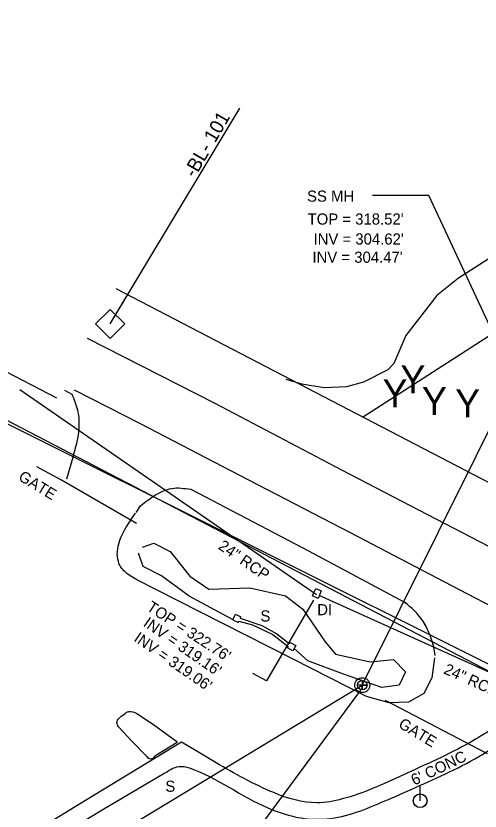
# Model space of a CAD drawing. Extents: x 2057786 to 2059508, y 687766 to 689280.
# Drawn here: x 2058201.2 to 2058367.9, y 688984.5 to 689270 of the extents above; entities that cross this region are included whole.
import ezdxf

# ---------------------------------------------------------------- set-up
doc = ezdxf.new("R2010")
doc.units = 0
for name, color, linetype in [('CTL Supplemental Horizontal and Vertical CELL', 7, 'Continuous'), ('CTL Supplemental Horizontal and Vertical Text', 7, 'Continuous'), ('Exist Horizontal Baseline Alignment Station Label', 7, 'Continuous'), ('Exist Horizontal Baseline Alignment Tick small', 7, 'Continuous'), ('Exist Other Culture Area Outline', 7, 'Continuous'), ('Exist Other Culture Gate', 7, 'Continuous'), ('Exist Other Culture Gate Text', 7, 'Continuous'), ('Exist Other Culture Sign CELL', 7, 'Continuous'), ('Exist Other Culture Sign Text', 7, 'Continuous'), ('Exist Property Line', 7, 'Continuous'), ('Exist Right of Way Line', 7, 'Continuous'), ('Exist Roads Curbs', 7, 'Continuous'), ('Exist Roads EOP', 7, 'Continuous'), ('Exist Roads EOP Other', 7, 'Continuous'), ('Exist Roads EOP Text', 7, 'Continuous'), ('Exist Roads EOT', 7, 'Continuous'), ('Exist Structure Minor Drop Inlet', 7, 'Continuous'), ('Exist Structure Minor Drop Inlet Leader', 7, 'Continuous'), ('Exist Structure Minor Drop Inlet Text', 7, 'Continuous'), ('Exist Structure Minor Pipes RCP 24 Inch', 7, 'Continuous'), ('Exist Structure Minor Pipes RCP 24 Inch Invert', 7, 'Continuous'), ('Exist Structure Minor Pipes RCP 24 Inch Text', 7, 'Continuous'), ('Exist Utilities Gas UG Line', 7, 'Continuous'), ('Exist Utilities Other Pole CELL', 7, 'Continuous'), ('Exist Utilities Power Pole CELL', 7, 'Continuous'), ('Exist Utilities Sanitary Sewer Forced Main', 7, 'Continuous'), ('Exist Utilities Sanitary Sewer Manhole CELL', 7, 'Continuous'), ('Exist Utilities Sanitary Sewer Manhole Leader', 7, 'Continuous'), ('Exist Utilities Sanitary Sewer Manhole Text', 7, 'Continuous'), ('Exist Utilities Sanitary Sewer Manhole Top Elevation', 7, 'Continuous'), ('Exist Utilities Sanitary Sewer UG Line', 7, 'Continuous'), ('Exist Utilities Sanitary Sewer UG Line Invert Elevation', 7, 'Continuous'), ('Old_Level_11', 7, 'Continuous')]:
    doc.layers.add(name, color=color, linetype=linetype)

# ---------------------------------------------------------------- blocks, each defined once
blk = doc.blocks.new('EXIST UTILITIES OTHER POLE')
at = {"layer": 'Exist Utilities Other Pole CELL'}
blk.add_circle((0, 0), 0.0493, dxfattribs=at)

msp = doc.modelspace()

# ---------------------------------------------------------------- linework, layer by layer
at = {"layer": 'CTL Supplemental Horizontal and Vertical CELL'}
msp.add_line((2058234.99, 689159.42), (2058234.99, 689159.42), dxfattribs=at)
msp.add_lwpolyline([(2058229.77, 689159.44), (2058235.01, 689164.68), (2058240.26, 689159.43), (2058235.02, 689154.19)], close=True, dxfattribs=at)
at = {"layer": 'Exist Horizontal Baseline Alignment Station Label'}
msp.add_line((2058234.99, 689159.42), (2058281.66, 689236.89), dxfattribs=at)
at = {"layer": 'Exist Horizontal Baseline Alignment Tick small'}
msp.add_line((2058234.99, 689159.42), (2058240.15, 689167.98), dxfattribs=at)
at = {"layer": 'Exist Other Culture Area Outline'}
for points in [[(2058246.61, 689079.34), (2058250.68, 689080.73), (2058256.6, 689077.74), (2058263.63, 689068.9), (2058270.52, 689064.23), (2058285.26, 689064.68), (2058298.06, 689061.85), (2058304.27, 689057.04), (2058312.26, 689045.32), (2058315.94, 689040.92), (2058328.41, 689038.12), (2058336.78, 689038.97), (2058341.17, 689034.55), (2058338.81, 689029.7), (2058332.66, 689028.94), (2058318.81, 689033.7), (2058305.99, 689038.49), (2058301.17, 689042.89)], [(2058279.01, 689053.33), (2058263.4, 689061.65), (2058253.53, 689069), (2058246.84, 689072.4), (2058245.17, 689077.19)]]:
    msp.add_lwpolyline(points, dxfattribs=at)
at = {"layer": 'Exist Other Culture Gate'}
for points in [[(2058244.49, 689087.74), (2058217.62, 689103.29), (2058208.69, 689108.15)], [(2058333.81, 689024.36), (2058370.5, 689005.16)]]:
    msp.add_lwpolyline(points, dxfattribs=at)
at = {"layer": 'Exist Other Culture Sign CELL'}
for p, q in [((2058279.07, 689053.22), (2058280, 689055.24)), ((2058280, 689055.24), (2058282.01, 689054.25)), ((2058280, 689055.24), (2058282.01, 689054.25)), ((2058279.07, 689053.22), (2058281.08, 689052.23)), ((2058281.08, 689052.23), (2058281.28, 689052.76)), ((2058281.28, 689052.76), (2058286.17, 689051.42)), ((2058281.78, 689053.82), (2058282.01, 689054.25)), ((2058281.78, 689053.82), (2058289.48, 689051.23)), ((2058281.78, 689053.82), (2058289.48, 689051.23)), ((2058286.17, 689051.42), (2058293.43, 689047.93)), ((2058289.48, 689051.23), (2058294.95, 689048.15)), ((2058293.43, 689047.93), (2058299.03, 689043.68)), ((2058294.95, 689048.15), (2058299.37, 689044.68)), ((2058298.77, 689043.12), (2058299.03, 689043.68)), ((2058299.37, 689044.68), (2058299.75, 689045.04)), ((2058299.75, 689045.04), (2058301.67, 689044.01)), ((2058301.67, 689044.01), (2058300.64, 689042.13)), ((2058300.64, 689042.13), (2058298.77, 689043.12))]:
    msp.add_line(p, q, dxfattribs=at)
at = {"layer": 'Exist Property Line'}
msp.add_line((2058325.64, 689126.02), (2058550.18, 689270.03), dxfattribs=at)
at = {"layer": 'Exist Right of Way Line'}
for p, q in [((2058422.34, 689075.69), (2058237.18, 689172.06)), ((2058394.64, 689022.47), (2058190.88, 689128.51))]:
    msp.add_line(p, q, dxfattribs=at)
at = {"layer": 'Exist Roads Curbs'}
for p, q in [((2058242.95, 689009.49), (2058238.03, 689014.76)), ((2058248.18, 689004.14), (2058242.95, 689009.49)), ((2058259.15, 689009.16), (2058251.06, 689004.22))]:
    msp.add_line(p, q, dxfattribs=at)
msp.add_lwpolyline([(2058244.59, 689019.53), (2058250.58, 689015.59), (2058258.57, 689009.8), (2058259.15, 689009.16)], dxfattribs=at)
msp.add_arc((2058249.6, 689004.98), 1.65, 210.5822, 332.4379, dxfattribs=at)
msp.add_spline([(2058238.03, 689014.76), (2058237.49, 689016.32), (2058239.91, 689019.23), (2058241.79, 689020.34), (2058244.59, 689019.53)], degree=3, dxfattribs=at)
at = {"layer": 'Exist Roads EOP'}
for p, q in [((2058218.69, 689135.67), (2058221.24, 689134.27)), ((2058221.59, 689111.54), (2058219.36, 689103.68)), ((2058264, 689100.06), (2058306.22, 689078.02)), ((2058264, 689100.06), (2058306.22, 689078.02)), ((2058244.37, 689091.77), (2058245.94, 689094.13)), ((2058244.37, 689091.77), (2058245.94, 689094.13)), ((2058242.99, 689089.77), (2058244.2, 689091.54)), ((2058306.22, 689078.02), (2058340.72, 689059.49)), ((2058306.22, 689078.02), (2058340.72, 689059.49)), ((2058351.02, 689044.23), (2058351.65, 689040.44)), ((2058351.02, 689044.23), (2058351.65, 689040.44))]:
    msp.add_line(p, q, dxfattribs=at)
for points in [[(2058500.05, 689011.62), (2058489.26, 689017.05), (2058484.73, 689021.35), (2058455.29, 689037.52), (2058440.84, 689043.12), (2058407.76, 689060.49), (2058364.53, 689082.85), (2058318.19, 689106.92), (2058272.72, 689130.83), (2058226.89, 689154.25)], [(2058351.54, 689039.62), (2058350.53, 689032.39), (2058347.64, 689026.75), (2058342.25, 689023.67), (2058335.25, 689023.45), (2058327.06, 689025.73), (2058300.52, 689039.22), (2058266.95, 689056.18), (2058244.68, 689067.61)], [(2058273.09, 689001.9), (2058265.37, 689006.55), (2058260.68, 689009.29), (2058228.92, 688990.01), (2058193.4, 688968.41)]]:
    msp.add_lwpolyline(points, dxfattribs=at)
msp.add_arc((2058326.02, 689038.47), 25.65, 12.9773, 55.0366, dxfattribs=at)
msp.add_ellipse((2058326.06, 689038.46), major_axis=(-1.28, 25.61), ratio=0.998882, start_param=4.889126, end_param=5.623594, dxfattribs=at)
for points in [[(2058221.24, 689134.27), (2058223.27, 689128.59), (2058223.66, 689120.69), (2058221.59, 689111.54)], [(2058245.94, 689094.13), (2058251.35, 689098.06), (2058257.13, 689100.39), (2058264, 689100.06)], [(2058245.94, 689094.13), (2058251.35, 689098.06), (2058257.13, 689100.39), (2058264, 689100.06)], [(2058244.68, 689067.61), (2058240.62, 689070.18), (2058238.3, 689073.25), (2058238.13, 689080.51), (2058242.99, 689089.77)], [(2058380.05, 689019.04), (2058364.29, 689009.19), (2058340.2, 688997.49), (2058318.41, 688988.88), (2058309.39, 688987.51), (2058293.79, 688991.16), (2058273.09, 689001.9)]]:
    msp.add_spline(points, degree=3, dxfattribs=at)
at = {"layer": 'Exist Roads EOP Other'}
msp.add_lwpolyline([(2058196.59, 688963.42), (2058232.13, 688984.97), (2058254.7, 688998.23)], dxfattribs=at)
msp.add_spline([(2058254.7, 688998.23), (2058259.03, 689000.39), (2058261.61, 689000.49), (2058265.31, 688999.4), (2058293.55, 688984.91), (2058311.62, 688981.63), (2058332.29, 688987.58), (2058343.11, 688992.31), (2058367.43, 689004.12), (2058388.89, 689018.98)], degree=3, dxfattribs=at)
at = {"layer": 'Exist Roads EOT'}
msp.add_lwpolyline([(2058398.26, 689044.39), (2058357.78, 689065.43), (2058321.41, 689084.43), (2058281.58, 689105), (2058245.94, 689123.54), (2058222.23, 689135.67)], dxfattribs=at)
at = {"layer": 'Exist Structure Minor Drop Inlet'}
msp.add_line((2058307.7, 689061.79), (2058308.91, 689064.48), dxfattribs=at)
msp.add_lwpolyline([(2058308.91, 689064.48), (2058310.83, 689063.65), (2058309.7, 689060.92), (2058307.7, 689061.79)], dxfattribs=at)
msp.add_lwpolyline([(2058308.91, 689064.48), (2058310.87, 689063.63), (2058309.7, 689060.92), (2058307.74, 689061.77)], close=True, dxfattribs=at)
at = {"layer": 'Exist Structure Minor Drop Inlet Leader'}
msp.add_lwpolyline([(2058308.02, 689060.28), (2058291.25, 689031.3), (2058286.28, 689033.92)], dxfattribs=at)
at = {"layer": 'Exist Structure Minor Pipes RCP 24 Inch'}
for points in [[(2058309.19, 689062.18), (2058202.62, 689135.84)], [(2058309.96, 689062.08), (2058418.79, 689012.98)]]:
    msp.add_lwpolyline(points, dxfattribs=at)
at = {"layer": 'Exist Utilities Gas UG Line'}
msp.add_line((2058073.82, 689206.96), (2058215.72, 689132.87), dxfattribs=at)
at = {"layer": 'Exist Utilities Power Pole CELL'}
for q in [(2058346.38, 688993.87), (2058346.38, 688988.25)]:
    msp.add_line((2058346.38, 688988.25), q, dxfattribs=at)
msp.add_circle((2058346.38, 688988.25), 2.45, dxfattribs=at)
at = {"layer": 'Exist Utilities Sanitary Sewer Forced Main'}
msp.add_line((2058156.64, 689144.24), (2058381.43, 689032.06), dxfattribs=at)
at = {"layer": 'Exist Utilities Sanitary Sewer Manhole CELL'}
msp.add_lwpolyline([(2058325.58, 689031.46), (2058325.58, 689028.04), (2058325.58, 689029.75), (2058327.29, 689029.75), (2058323.87, 689029.75)], dxfattribs=at)
for radius in [2.69, 1.71]:
    msp.add_circle((2058325.58, 689029.75), radius, dxfattribs=at)
at = {"layer": 'Exist Utilities Sanitary Sewer Manhole Leader'}
for points in [[(2058378.41, 689143.51), (2058349.47, 689205.57), (2058329.29, 689205.57)], [(2058325, 689027.94), (2058288.11, 688978.04), (2058273.77, 688978.04)]]:
    msp.add_lwpolyline(points, dxfattribs=at)
at = {"layer": 'Exist Utilities Sanitary Sewer UG Line'}
for points in [[(2058325.58, 689029.75), (2058380.19, 689139.38)], [(2058053.44, 688865.14), (2058325.58, 689029.75)]]:
    msp.add_lwpolyline(points, dxfattribs=at)
at = {"layer": 'Old_Level_11'}
msp.add_lwpolyline([(2058418.33, 689210.03), (2058412.06, 689209.77), (2058403.9, 689207.97), (2058394.95, 689202.65), (2058387.03, 689195.4), (2058375.19, 689185.57), (2058370.39, 689182.42), (2058360.15, 689175.93), (2058352.39, 689169.62), (2058341.28, 689155.23), (2058336.89, 689145.21), (2058334.75, 689142.91), (2058326.07, 689138.56), (2058319.95, 689136.9), (2058311.9, 689136.54), (2058303.94, 689137.79), (2058298.21, 689139.52)], dxfattribs=at)

# ---------------------------------------------------------------- block references
at = {"layer": 'Exist Utilities Other Pole CELL', "xscale": 50, "yscale": 50}
msp.add_blockref('EXIST UTILITIES OTHER POLE', (2058346.38, 688988.25), dxfattribs=at)

# ---------------------------------------------------------------- texts
at = {"layer": 'CTL Supplemental Horizontal and Vertical Text'}
msp.add_text('-BL- 101', height=5, rotation=59.9041, dxfattribs=at).set_placement((2058265.43, 689211.62))
at = {"layer": 'Exist Other Culture Gate Text'}
for p in [(2058201.74, 689103.61), (2058338.25, 689014.84)]:
    msp.add_text('GATE', height=4, rotation=328.6652, dxfattribs=at).set_placement(p)
at = {"layer": 'Exist Other Culture Sign Text'}
for p in [(2058289.02, 689052.6), (2058254.86, 688991.47)]:
    msp.add_text('S', height=4, rotation=0, dxfattribs=at).set_placement(p)
at = {"layer": 'Exist Roads EOP Text'}
msp.add_text("6' CONC", height=4, rotation=25.6164, dxfattribs=at).set_placement((2058344.28, 688993.64))
at = {"layer": 'Exist Structure Minor Drop Inlet Text'}
for s, rotation, p in [("TOP = 322.76'", 326.9829, (2058247.84, 689056.88)), ('DI', 0, (2058309.41, 689054.87))]:
    msp.add_text(s, height=4, rotation=rotation, dxfattribs=at).set_placement(p)
at = {"layer": 'Exist Structure Minor Pipes RCP 24 Inch Invert'}
for s, p in [("INV = 319.16'", (2058246.65, 689051.23)), ("INV = 319.06'", (2058243.25, 689045.81))]:
    msp.add_text(s, height=4, rotation=325.3474, dxfattribs=at).set_placement(p)
at = {"layer": 'Exist Structure Minor Pipes RCP 24 Inch Text'}
for rotation, p in [(325.3474, (2058273.55, 689078.9)), (335.7174, (2058354.53, 689034.07))]:
    msp.add_text('24" RCP', height=4, rotation=rotation, dxfattribs=at).set_placement(p)
at = {"layer": 'Exist Utilities Sanitary Sewer Manhole Text'}
msp.add_text('SS MH', height=4, rotation=0, dxfattribs=at).set_placement((2058305.75, 689203.33))
at = {"layer": 'Exist Utilities Sanitary Sewer Manhole Top Elevation'}
msp.add_text("TOP = 318.52'", height=4, rotation=0, dxfattribs=at).set_placement((2058305.96, 689195.1))
at = {"layer": 'Exist Utilities Sanitary Sewer UG Line Invert Elevation'}
for s, p in [("INV = 304.62'", (2058308.08, 689187.94)), ("INV = 304.47'", (2058307.69, 689181.4))]:
    msp.add_text(s, height=4, rotation=0, dxfattribs=at).set_placement(p)
at = {"layer": 'Old_Level_11'}
for p in [(2058339.32, 689134.52), (2058332.9, 689129.55), (2058347.04, 689126.74), (2058358.96, 689125.96)]:
    msp.add_text('Y', height=10, dxfattribs=at).set_placement(p)

doc.saveas('drawing.dxf')
